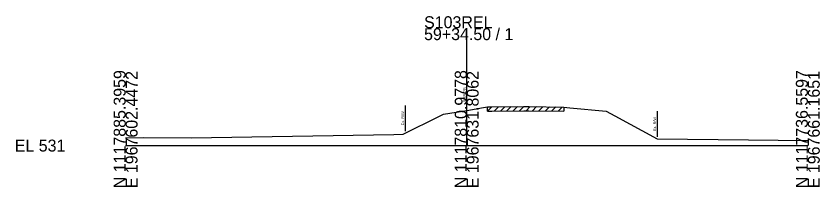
# Model space of a CAD drawing. Extents: x -26 to 163, y -10 to 24518.
# Drawn here: x -25.7 to 162.8, y 9990.3 to 10030.4 of the extents above; entities that cross this region are included whole.
import ezdxf

# ---------------------------------------------------------------- set-up
doc = ezdxf.new("R2010")
doc.units = 0
for name, color, linetype in [('RD_GPK_XS_Cell', 7, 'Continuous'), ('RD_XS_ExGround', 7, 'Continuous'), ('RD_XS_ExPaveRet', 7, 'Continuous'), ('RD_XS_ExRW', 7, 'Continuous'), ('RD_XS_TX_Elev_EX', 7, 'Continuous')]:
    doc.layers.add(name, color=color, linetype=linetype)

msp = doc.modelspace()

# ---------------------------------------------------------------- linework, layer by layer
at = {"layer": 'RD_GPK_XS_Cell'}
for p, q in [((80, 10000), (80, 10027.52)), ((0, 10000), (80, 10000)), ((80, 10000), (160, 10000))]:
    msp.add_line(p, q, dxfattribs=at)
at = {"layer": 'RD_XS_ExGround'}
msp.add_lwpolyline([(0, 10001.8), (4.28, 10001.89), (15.4, 10001.81), (62.94, 10002.61), (65.06, 10002.66), (73.6, 10006.9), (74.58, 10007.38), (80, 10008.26), (83.91, 10008.89), (84.91, 10009.05), (85.87, 10009.06), (93.43, 10009.17), (94.57, 10009.15), (102.76, 10009.04), (104.22, 10008.88), (112.71, 10008.09), (114.75, 10006.98), (124.66, 10001.56), (146.1, 10001.31), (160, 10001.22)], dxfattribs=at)
at = {"layer": 'RD_XS_ExPaveRet'}
for p, q in [((84.91, 10008.05), (85.92, 10009.06)), ((84.91, 10008.05), (84.91, 10009.05)), ((84.91, 10008.05), (85.87, 10008.06)), ((85.87, 10008.06), (93.43, 10008.17)), ((86.41, 10008.07), (87.42, 10009.09)), ((87.91, 10008.09), (88.92, 10009.11)), ((89.41, 10008.11), (90.42, 10009.13)), ((90.91, 10008.14), (91.92, 10009.15)), ((92.41, 10008.16), (93.42, 10009.17)), ((93.43, 10008.17), (94.57, 10008.15)), ((93.91, 10008.16), (94.89, 10009.15)), ((94.57, 10008.15), (102.76, 10008.04)), ((95.41, 10008.14), (96.39, 10009.13)), ((96.91, 10008.12), (97.89, 10009.11)), ((98.41, 10008.1), (99.39, 10009.08)), ((99.91, 10008.08), (100.89, 10009.06)), ((101.41, 10008.06), (102.39, 10009.04)), ((102.76, 10009.04), (102.76, 10008.04))]:
    msp.add_line(p, q, dxfattribs=at)
at = {"layer": 'RD_XS_ExRW'}
for p, q in [((65.56, 10009.4), (65.56, 10003.4)), ((124.66, 10008.06), (124.66, 10002.06))]:
    msp.add_line(p, q, dxfattribs=at)

# ---------------------------------------------------------------- texts
at = {"layer": 'RD_GPK_XS_Cell'}
for s, p in [('S103REL', (70, 10027.52)), ('59+34.50 / 1', (70, 10024.72)), ('EL 531', (-26, 9998.6))]:
    msp.add_text(s, height=2.8, dxfattribs=at).set_placement(p)
for s, p in [('N 1117885.3959', (0, 9990)), ('E 1967602.4472', (2.8, 9990)), ('N 1117810.9778', (80, 9990)), ('E 1967631.8062', (82.8, 9990)), ('N 1117736.5597', (160, 9990)), ('E 1967661.1651', (162.8, 9990))]:
    msp.add_text(s, height=2.8, rotation=90, dxfattribs=at).set_placement(p)
at = {"layer": 'RD_XS_ExRW'}
for p in [(65.31, 10004.75), (124.41, 10003.4)]:
    msp.add_text('Ex. R/W ', height=0.65, rotation=90, dxfattribs=at).set_placement(p)
at = {"layer": 'RD_XS_TX_Elev_EX'}
msp.add_text('539.26', height=0.8, rotation=90, dxfattribs=at).set_placement((79.9, 10010.26))

doc.saveas('drawing.dxf')
